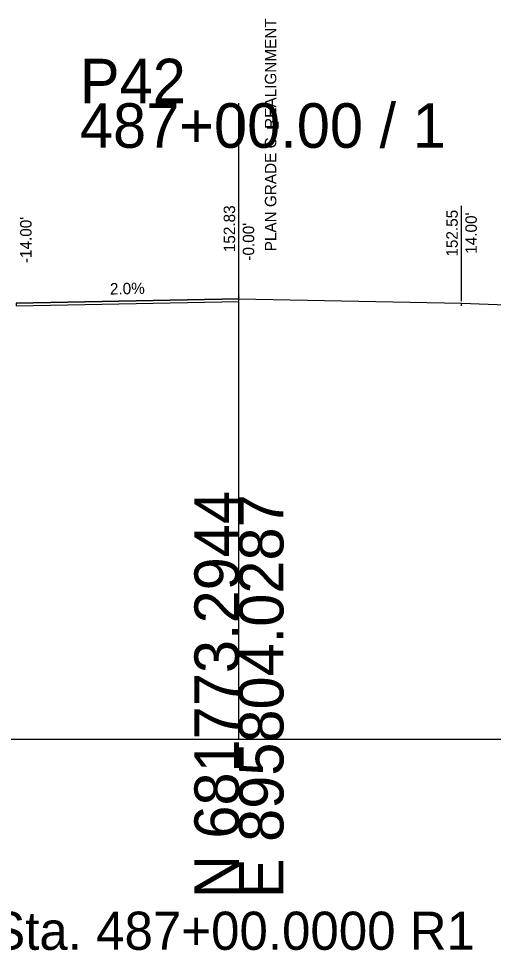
# Model space of a CAD drawing. Extents: x -100 to 4303, y -13 to 10775.
# Drawn here: x 3136.1 to 3166, y 5486.7 to 5545.3 of the extents above; entities that cross this region are included whole.
import ezdxf

# ---------------------------------------------------------------- set-up
doc = ezdxf.new("R2010")
doc.units = 0
for name, color, linetype in [('ASHPALT_12_5MM1', 7, 'Continuous'), ('Default', 7, 'Continuous'), ('Draft_XS_Text', 7, 'Continuous'), ('DTM CONTOURS_MAJOR', 7, 'Continuous'), ('DTM_X_GROUND', 7, 'Continuous'), ('XS_CELL', 7, 'Continuous'), ('XS_P_TX_CLEARZONE', 7, 'Continuous'), ('XS_P_TX_FS_BS', 7, 'Continuous')]:
    doc.layers.add(name, color=color, linetype=linetype)

msp = doc.modelspace()

# ---------------------------------------------------------------- linework, layer by layer
at = {"layer": 'ASHPALT_12_5MM1'}
msp.add_line((3164, 5527.257), (3164, 5527.424), dxfattribs=at)
at = {"layer": 'Default'}
msp.add_lwpolyline([(3150, 5527.704), (3136, 5527.424), (3136, 5527.424), (3136, 5527.257), (3150, 5527.537), (3150, 5527.537), (3150, 5527.704), (3150, 5527.704), (3150, 5527.704)], dxfattribs=at)
at = {"layer": 'DTM_X_GROUND'}
for p, q in [((3136, 5527.424), (3150, 5527.704)), ((3150, 5527.704), (3164, 5527.424)), ((3164, 5527.424), (3168.595, 5527.24))]:
    msp.add_line(p, q, dxfattribs=at)
at = {"layer": 'XS_CELL'}
for p, q in [((3150, 5500), (3150, 5540)), ((3150, 5500), (3150, 5540)), ((3000, 5500), (3150, 5500)), ((3000, 5500), (3150, 5500)), ((3150, 5500), (3300, 5500)), ((3150, 5500), (3300, 5500))]:
    msp.add_line(p, q, dxfattribs=at)
at = {"layer": 'XS_P_TX_CLEARZONE'}
for p, q in [((3150, 5527.829), (3150, 5533.829)), ((3150, 5527.829), (3150, 5533.829)), ((3150, 5527.829), (3150, 5533.829)), ((3150, 5527.829), (3150, 5533.829)), ((3150, 5527.829), (3150, 5533.829)), ((3164, 5527.549), (3164, 5533.549)), ((3164, 5527.549), (3164, 5533.549))]:
    msp.add_line(p, q, dxfattribs=at)

# ---------------------------------------------------------------- texts
at = {"layer": 'Draft_XS_Text'}
msp.add_text('Sta. 487+00.0000 R1', height=2.4, dxfattribs=at).set_placement((3134.42, 5486.75))
at = {"layer": 'DTM CONTOURS_MAJOR'}
msp.add_text('X', height=0.12, dxfattribs=at).set_placement((3149.961, 5527.769))
msp.add_text('X', height=0.12, dxfattribs=at).set_placement((3149.961, 5527.769))
at = {"layer": 'XS_CELL'}
for s, p in [('P42', (3140, 5540)), ('P42', (3140, 5540)), ('487+00.00 / 1', (3140, 5537.2)), ('487+00.00 / 1', (3140, 5537.2))]:
    msp.add_text(s, height=2.8, dxfattribs=at).set_placement(p)
for s, p in [('N 681773.2944', (3150, 5490)), ('N 681773.2944', (3150, 5490)), ('E 895804.0287', (3152.8, 5490)), ('E 895804.0287', (3152.8, 5490))]:
    msp.add_text(s, height=2.8, rotation=90, dxfattribs=at).set_placement(p)
at = {"layer": 'XS_P_TX_CLEARZONE'}
for s, p in [('PLAN GRADE C  REALIGNMENT', (3152.352, 5530.687)), ('L', (3152.492, 5538.332)), ('152.83', (3149.76, 5530.633)), ('152.83', (3149.76, 5530.633)), ('152.83', (3149.76, 5530.633)), ('152.83', (3149.76, 5530.633)), ('152.83', (3149.76, 5530.633)), ('152.55', (3163.76, 5530.353)), ('152.55', (3163.76, 5530.353)), ("-14.00'", (3136.96, 5529.945)), ("-14.00'", (3136.96, 5529.945)), ("-14.00'", (3136.96, 5529.945)), ("14.00'", (3164.96, 5530.534)), ("14.00'", (3164.96, 5530.534)), ("-0.00'", (3150.96, 5530.101))]:
    msp.add_text(s, height=0.72, rotation=90, dxfattribs=at).set_placement(p)
at = {"layer": 'XS_P_TX_FS_BS'}
msp.add_text('2.0%', height=0.72, rotation=1.14576, dxfattribs=at).set_placement((3141.892, 5527.966))

doc.saveas('drawing.dxf')
